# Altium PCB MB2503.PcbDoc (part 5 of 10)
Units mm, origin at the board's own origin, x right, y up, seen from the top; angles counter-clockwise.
Board outline 127 x 97 mm, 6 copper layers (Top Layer, Signal Layer 1, Signal Layer 2, Signal Layer 3, Signal Layer 4, Bottom Layer), stack 1.557 mm thick; 572 components, 468 nets, 2377 pads, 1704 vias.
Unrouted connection lines stored in the file: 3.
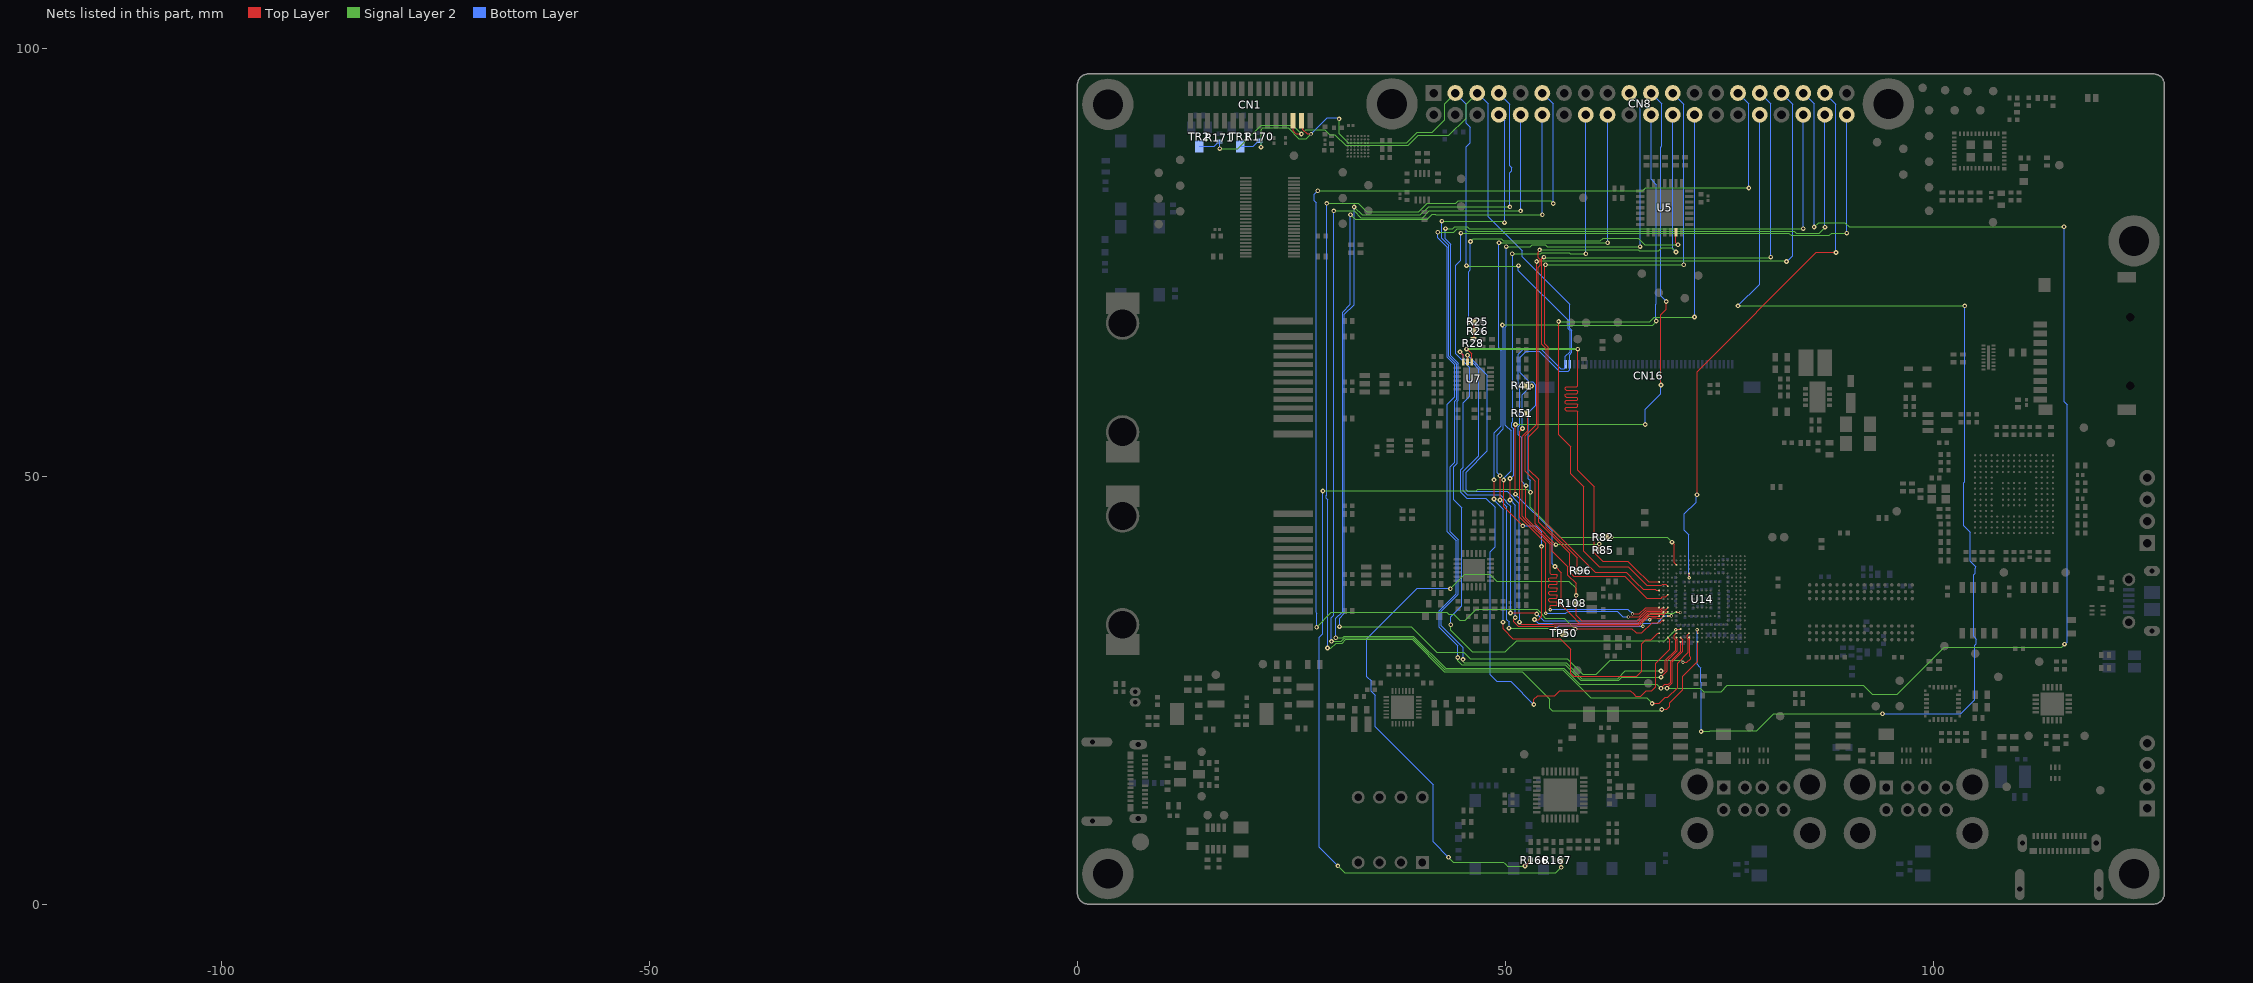
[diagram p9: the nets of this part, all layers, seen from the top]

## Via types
v1: diameter 0.55, hole 0.25, Top Layer to Bottom Layer, 1335 vias
v2: diameter 0.4, hole 0.2, Top Layer to Bottom Layer, 262 vias
v3: diameter 0.5, hole 0.2, Top Layer to Bottom Layer, 51 vias
v4: diameter 0.26, hole 0.1, Top Layer to Signal Layer 1, tented both sides, 29 vias
v5: diameter 0.5, hole 0.25, Top Layer to Bottom Layer, 18 vias
v6: diameter 0.4, hole 0.2, Top Layer to Bottom Layer, tented both sides, 9 vias

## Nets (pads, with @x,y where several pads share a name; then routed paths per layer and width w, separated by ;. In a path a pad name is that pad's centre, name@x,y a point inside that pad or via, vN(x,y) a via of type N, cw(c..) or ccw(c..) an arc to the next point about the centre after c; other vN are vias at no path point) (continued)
ETH2_NRST: R25.1 R26.1 R28.1 U5.27 | length 38.7
  Top Layer w0.1: v1(45.725,68.025) R25.1@46.35,68.025 R26.1@46.35,66.95 46.35,66.075 R28.1@46.275,66 ; U5.27@69.925,78.525 69.925,77.3 v1(70.175,77.05)
  Signal Layer 2 w0.1: v1(45.925,77.425) 46.225,77.725 49.5,77.725 49.725,77.5 61.1,77.5 61.425,77.825 65.5,77.825 66.275,77.05 v1(70.175,77.05)
  Bottom Layer w0.1: v1(45.725,68.025) 45.725,73.9 45.925,74.1 v1(45.925,77.425)
ETH2_RXD0: R41.1 U14.N2 | length 43.6
  Top Layer w0.075: 65.175,33.55 65.625,33.55 66.479,34.404 68.077,34.404 68.323,34.65 U14.N2@68.475,34.65
  Top Layer w0.1: v1(52,55.575) 51.7,55.275 51.7,45.2 54.725,42.175 v2(54.725,33.975) ; R41.1@52.425,60.575 52.45,60.55 v1(53.05,60.55) ; v2(64.375,33.55) 65.175,33.55
  Bottom Layer w0.1: v1(52,55.575) 52,59.5 v1(53.05,60.55) ; v2(54.725,33.975) 57.075,33.975 57.325,34.225 63.05,34.225 63.725,33.55 v2(64.375,33.55)
ETH2_RXD1: R51.1 U14.N1 | length 46.5
  Top Layer w0.075: 65.175,33.9 65.65,33.9 66.4,34.65 U14.N1@67.975,34.65
  Top Layer w0.1: R51.1@52.425,57.35 52.6,57.175 52.6,55.325 51.95,54.675 51.95,45.3 52.205,45.045 55.225,42.024 55.225,38.75 55.225,38.65 55.325,38.55 55.975,38.55 56.075,38.45 56.075,38.25 55.975,38.15 55.225,38.15 55.175,38.15 55.075,38.05 55.075,37.85 55.175,37.75 55.225,37.75 55.975,37.75 56.075,37.65 56.075,37.45 55.975,37.35 55.225,37.35 55.175,37.35 55.075,37.25 55.075,37.05 55.175,36.95 55.225,36.95 55.975,36.95 56.075,36.85 56.075,36.65 55.975,36.55 55.225,36.55 55.175,36.55 55.075,36.45 55.075,36.25 55.175,36.15 55.225,36.15 55.975,36.15 56.075,36.05 56.075,35.85 55.975,35.75 55.225,35.75 55.175,35.75 55.075,35.65 55.075,35.45 55.175,35.35 55.225,35.35 55.975,35.35 56.075,35.25 56.075,35.05 55.975,34.95 55.325,34.95 55.225,34.85 55.225,34.55 55.25,34.525 55.253,34.522 v2(55.253,34.402) ; v2(64.854,33.908) 64.863,33.9 65.175,33.9
  Bottom Layer w0.1: v2(55.253,34.402) 55.301,34.45 64.313,34.45 v2(64.854,33.908)
ETH2_TX_EN: U7.16 U14.G1 | length 58.9
  Top Layer w0.075: 65.175,39.2 66.725,37.65 U14.G1@67.975,37.65
  Top Layer w0.1: v1(45.45,64.85) 45.55,64.85 46.075,64.325 U7.16@46.075,63.35 ; v1(58.45,64.85) 58.45,60.975 58.45,60.85 58.45,60.55 58.35,60.45 57.125,60.45 57.025,60.35 57.025,60.15 57.125,60.05 58.35,60.05 58.45,59.95 58.45,59.75 58.35,59.65 57.125,59.65 57.025,59.55 57.025,59.35 57.125,59.25 58.35,59.25 58.45,59.15 58.45,58.95 58.35,58.85 57.125,58.85 57.025,58.75 57.025,58.55 57.125,58.45 58.35,58.45 58.45,58.35 58.45,58.15 58.35,58.05 57.125,58.05 57.025,57.95 57.025,57.75 57.125,57.65 58.35,57.65 58.45,57.55 58.45,57.45 58.45,50.675 60.375,48.75 60.375,41.05 61.375,40.05 64.325,40.05 65.175,39.2
  Signal Layer 2 w0.219: v1(45.45,64.85) v1(58.45,64.85)
ETH2_TXD0: U7.17 U14.P3 | length 57.4
  Top Layer w0.075: 65.175,32.7 65.575,32.7 66.772,33.897 68.572,33.897 68.825,34.15 U14.P3@68.975,34.15
  Top Layer w0.1: U7.17@45.575,63.35 v1(45.575,64.125) ; v1(51.653,32.952) 51.627,32.952 51.625,32.95 51.875,32.7 55.566,32.7 55.616,32.75 58.434,32.75 58.484,32.7 65.175,32.7
  Bottom Layer w0.1: v1(45.575,64.125) 47.9,61.8 47.9,52.95 45.4,50.45 45.4,48.4 45.575,48.225 50.2,48.225 51.625,46.8 51.625,44.401 51.6,44.376 51.6,34 51.653,33.947 v1(51.653,32.952)
ETH2_TXD1: U7.18 U14.R2 | length 56.9
  Top Layer w0.075: v2@66.898,33.225 66.905,33.225 67.161,33.481 67.644,33.481 67.725,33.4 68.225,33.4 U14.R2@68.475,33.65
  Top Layer w0.09: v2(66.875,33.225) v2@66.898,33.225
  Top Layer w0.1: v1(44.7,64.525) 45.075,64.15 U7.18@45.075,63.35 ; v1(50.6,34.025) 53.65,34.025 53.669,34.006 v1(53.669,33.9)
  Bottom Layer w0.1: v1(44.7,64.525) 45.1,64.125 45.1,63.85 45.641,63.309 46.108,63.309 46.9,62.517 46.9,52.4 45.1,50.6 45.1,48.275 45.55,47.825 49.4,47.825 50.125,47.1 50.125,46.95 50.6,46.475 v1(50.6,34.025) ; v1(53.669,33.9) 54.469,33.1 65.4,33.1 65.525,33.225 v2(66.875,33.225)
EXP_GPIO2: CN1.14 CN8.3 CN16.40 R108.1 R166.1 R170.2 TR1.3 U14.N3 | length 200.5
  Top Layer w0.075: 65.175,33.1 65.425,33.1 66.56,34.235 68.196,34.235 68.358,34.397 68.722,34.397 U14.N3@68.975,34.65
  Top Layer w0.09: v1(52.4,48.9) 52.4,45.125 55.475,42.05 55.475,41.225 57.3,39.4 57.3,38.45 58.275,37.475 R108.1@58.275,35.15 58.275,33.775 58.95,33.1 65.175,33.1
  Top Layer w0.1: CN1.14@26.2,91.525 26.304,91.421 26.304,90.509 26.825,89.987 27.287,89.987 v2(27.294,89.994) ; v1(52.3,4.45) R166.1@52.975,5.125
  Signal Layer 2 w0.1: v1(21.45,88.45) 21.45,90.475 21.675,90.7 24.625,90.7 25.875,89.45 26.75,89.45 v2(27.294,89.994) ; v1(30.573,91.75) 30.573,89.997 31.63,88.94 38.47,88.94 39.73,90.2 ; 39.95,90.2 39.73,90.2 ; v1(43.35,5.475) 43.925,4.9 49.775,4.9 49.9,4.775 ; v1(43.575,36.85) 45.25,38.525 48.2,38.525 48.975,37.75 57.425,37.75 58.275,36.9 v1(58.275,36.075) ; CN8.3@44.16,94.77 42.9,93.51 42.9,91.625 41.475,90.2 39.73,90.2 ; v1(45.45,74.6) 45.525,74.525 51.45,74.525 v1(51.525,74.6) ; 49.901,4.775 50.15,4.526 ; 50.15,4.525 50.225,4.45 v1(52.3,4.45)
  Bottom Layer w0.09: 51.9,51.5 51.9,49.4 v1(52.4,48.9)
  Bottom Layer w0.1: TR1.3@19,88.55 20.525,88.55 21.175,89.2 R170.2@21.3,89.2 21.45,89.05 v1(21.45,88.45) ; v2(27.294,89.994) 29.2,91.9 30.302,91.9 30.452,91.75 v1(30.573,91.75) ; 34.3,26.1 33.825,26.575 33.825,31.025 39.725,36.925 43.45,36.925 v1@43.475,36.95 ; 34.325,26.1 34.325,24.875 34.8,24.4 34.8,20.708 41.55,13.958 41.55,7.3 43.35,5.5 v1(43.35,5.475) ; CN8.3@44.16,94.77 45.45,93.48 45.45,91.214 45.914,90.75 45.914,88.957 45.45,88.493 v1(45.45,74.6) ; v1(51.525,74.6) 51.525,74 57.325,68.2 57.325,67.23 57.575,66.98 57.575,64.56 57.025,64.01 CN16.40@57.025,63.1 56.925,63 56.925,62.609 56.866,62.55 56.45,62.55 54.125,64.875 52.137,64.875 51.525,64.263 51.525,60.648 51.675,60.498 51.675,55.937 51.525,55.787 51.525,54.85 51.9,54.475 51.9,51.5
EXP_GPIO3: CN1.13 CN8.5 CN16.39 R82.1 R167.1 R171.2 TR2.3 U14.C5 | length 223.5
  Top Layer w0.075: v1(69.475,42.3) 69.721,42.054 69.721,39.904 U14.C5@69.975,39.65
  Top Layer w0.1: CN1.13@25.2,91.525 25.2,90.362 25.412,90.15 25.575,89.987 v1(26.163,89.987) ; v1@30.412,4.463 v1(30.425,4.475) ; v1(56.525,4.3) R167.1@56.525,5.125 ; R82.1@61.875,42.875 v2(62.45,42.875)
  Signal Layer 2 w0.09: 65.175,42.875 68.9,42.875 v1(69.475,42.3)
  Signal Layer 2 w0.1: v1(16.625,88.275) 18.75,88.275 21.48,91.005 25.145,91.005 v1(26.163,89.987) 26.671,90.496 28.907,90.496 29.477,89.925 30.085,89.925 31.36,88.65 38.63,88.65 39.83,89.85 43.4,89.85 45.4,91.85 45.4,93.47 CN8.5@46.7,94.77 ; v1(28.676,48.277) 46.573,48.277 46.575,48.275 46.775,48.475 52.575,48.475 v1(52.925,48.125) 52.925,46.35 56.4,42.875 v2(62.45,42.875) 65.175,42.875 ; v1(30.425,4.475) 31.25,3.65 55.875,3.65 v1(56.525,4.3)
  Bottom Layer w0.1: TR2.3@14.25,88.55 15.98,88.55 16.53,89.1 R171.2@16.625,89.1 v1(16.625,88.275) ; v1(28.676,48.277) 28.676,31.601 28.251,31.176 28.251,6.624 v1@30.4,4.475 ; CN8.5@46.7,94.77 47.975,93.495 47.975,80.325 51.95,76.35 51.95,75.65 57.525,70.075 57.525,67.313 57.775,67.063 57.775,64.46 57.525,64.21 CN16.39@57.525,63.1 57.525,62.451 57.336,62.262 56.288,62.262 53.975,64.575 52.425,64.575 51.725,63.875 51.725,62.106 52.787,61.044 53.181,61.044 53.575,60.65 53.575,58.3 52.7,57.425 52.7,49.725 52.925,49.5 v1(52.925,48.125)
EXP_GPIO4: CN8.7 U14.Y8 | length 129.6
  Top Layer w0.075: v2(70.75,28.25) 71.194,28.25 71.632,28.688 71.632,28.918 71.559,28.991 71.559,31.029 71.475,31.113 U14.Y8@71.475,31.15
  Signal Layer 2 w0.09: v1(30.625,32.425) 38.999,32.425 41.976,29.448 45.152,29.448 45.925,28.675 57.25,28.675 59.05,26.875 ; 41.023,81.475 v1(50.525,81.475) ; 65.175,28.514 70.536,28.514 70.775,28.275 v2@70.775,28.25
  Signal Layer 2 w0.1: v1(32.326,81.454) 32.351,81.454 33.28,80.525 40.073,80.525 41.023,81.475 ; 59.05,26.875 60.6,26.875 62.239,28.514 65.175,28.514
  Bottom Layer w0.09: v1(30.625,32.425) 30.625,33.425 31.2,34 31.2,68.9 32.326,70.026 v1(32.326,81.454) ; CN8.7@49.24,94.77 50.525,93.485 50.525,86.25 50.747,86.028 50.747,85.68 50.525,85.458 v1(50.525,81.475)
EXP_GPIO5: CN8.29 TP50.1 U14.T2 | length 159
  Top Layer w0.075: 65.175,31.8 65.275,31.7 65.947,31.7 67.151,32.904 67.466,32.904 68.077,32.904 68.3,33.127 68.452,33.127 U14.T2@68.475,33.15
  Top Layer w0.1: TP50.1@56.825,31.675 57.275,32.125 v1(58.175,32.125) 58.25,32.2 64.775,32.2 65.175,31.8
  Signal Layer 2 w0.1: v1(27.95,32.35) 29.675,34.075 43.15,34.075 43.375,33.85 43.975,33.85 44.65,33.175 45.33,33.175 46.605,34.45 47.975,34.45 53.72,34.45 54.3,33.87 54.3,33.799 54.674,33.425 56.875,33.425 56.95,33.35 ; v1(28.075,83.35) 66.075,83.35 66.425,83.7 78.425,83.7 v1(78.45,83.675) ; 56.95,33.349 v1(58.175,32.125)
  Bottom Layer w0.1: v1(27.95,32.35) 27.95,34 27.875,34.075 27.875,81.979 27.651,82.203 27.651,82.926 v1(28.075,83.35) ; CN8.29@77.18,94.77 78.45,93.5 v1(78.45,83.675)
EXP_GPIO6: CN8.31 R96.2 | length 85
  Top Layer w0.1: v1(54.5,75.6) 54.35,75.6 54.275,75.525 54.275,65.4 54.8,64.875 54.8,44.05 58.375,40.475 R96.2@58.375,38.95
  Signal Layer 2 w0.1: v1(54.5,75.6) 54.45,75.6 54.4,75.55 80.95,75.55 v1(81,75.6)
  Bottom Layer w0.1: CN8.31@79.72,94.77 81,93.49 v1(81,75.6)
EXP_GPIO7: CN8.26 U14.H3 | length 79.4
  Top Layer w0.075: 65.175,38.625 66.524,37.276 67.699,37.276 67.741,37.235 68.211,37.235 68.373,37.397 68.728,37.397 U14.H3@68.975,37.15
  Top Layer w0.1: v1(56.225,68.075) 56.225,54.85 57.65,53.425 57.65,50.275 59.15,48.775 59.15,41.25 60.975,39.425 64.375,39.425 65.175,38.625
  Signal Layer 2 w0.1: v1(56.225,68.075) 66.875,68.075 67.4,68.6 v1(72.1,68.6)
  Bottom Layer w0.1: v1(72.1,68.6) CN8.26@72.1,92.23
EXP_GPIO8: CN8.24 U14.K3 | length 85.8
  Top Layer w0.075: 65.175,37.075 66.515,35.735 68.185,35.735 68.354,35.904 68.729,35.904 U14.K3@68.975,36.15
  Top Layer w0.1: v1(54,76.45) 54,76.328 53.825,76.153 53.825,75.524 54.075,75.274 54.075,74.625 53.85,74.4 53.85,55.725 52.75,54.625 52.75,50.775 53.9,49.625 53.9,44.625 57.55,40.975 57.55,38.75 57.975,38.325 63.925,38.325 65.175,37.075
  Signal Layer 2 w0.1: v1(54,76.45) 65.524,76.45 65.649,76.325 67.907,76.325 68.282,76.7 69.425,76.7 v1(69.925,76.2)
  Bottom Layer w0.1: CN8.24@69.56,92.23 69.56,76.565 v1(69.925,76.2)
EXP_GPIO9: CN8.21 U14.P2 | length 92.6
  Top Layer w0.075: 65.175,32.9 65.515,32.9 66.681,34.066 68.266,34.066 68.327,34.127 68.452,34.127 U14.P2@68.475,34.15
  Top Layer w0.1: v1(51.175,47.9) v1(51.175,56.05) ; v1(55.8,39.45) 56.525,38.725 56.525,35.426 56.428,35.329 56.428,34.926 56.677,34.677 56.824,34.677 57.8,33.701 57.8,33.675 58.575,32.9 65.175,32.9 ; v1(68.175,60.65) 68.175,68.866 68.808,69.499 68.808,70.417 v1(68.8,70.425)
  Signal Layer 2 w0.1: v1(51.175,56.05) v1(66.35,56.05)
  Bottom Layer w0.1: v1(51.175,47.9) 55.475,43.6 55.475,39.775 v1(55.8,39.45) ; v1(66.35,56.05) 66.35,57.808 68.175,59.633 v1(68.175,60.65) ; CN8.21@67.02,94.77 68.3,93.49 68.3,88.595 68.15,88.445 68.15,71.075 v1(68.8,70.425)
EXP_GPIO10: CN8.19 U14.R3 | length 98.9
  Top Layer w0.09: U14.R3@68.975,33.65 68.988,33.663 69.388,33.663 v2(69.4,33.675)
  Top Layer w0.1: v1(49.8,49.55) 49.8,46.425 v1(52.025,44.2) ; v1(53.4,33.25) 53.9,33.25 54.275,33.625 54.275,41.325 54.225,41.375 v1(54.225,41.8)
  Signal Layer 2 w0.1: v1(50.1,76.825) 52.9,76.825 53.125,77.05 54.686,77.05 54.911,76.825 v1(65.75,76.825)
  Bottom Layer w0.09: 65.175,32.825 67.725,32.825 68.575,33.675 v2(69.4,33.675)
  Bottom Layer w0.1: v1(49.8,49.55) 49.8,49.775 50.675,50.65 50.675,55.3 50,55.975 50,67.424 50.075,67.499 50.075,76.8 v1(50.1,76.825) ; v1(52.025,44.2) 53.525,44.2 54.225,43.5 v1(54.225,41.8) ; v1(53.4,33.25) 53.825,32.825 65.175,32.825 ; CN8.19@64.48,94.77 65.75,93.5 v1(65.75,76.825)
EXP_GPIO11: CN8.23 U14.J1 | length 83.5
  Top Layer w0.075: 65.175,37.675 66.081,36.769 67.489,36.769 67.608,36.65 U14.J1@67.975,36.65
  Top Layer w0.1: v1(54.7,74.7) 54.614,74.614 54.614,74.43 54.6,74.416 54.6,65.475 55,65.075 55,44.25 60.5,38.75 64.1,38.75 65.175,37.675
  Signal Layer 2 w0.1: v1(54.7,74.7) v1(70.85,74.7)
  Bottom Layer w0.1: CN8.23@69.56,94.77 70.85,93.48 v1(70.85,74.7)
EXP_GPIO12: CN8.32 U14.W10 | length 142.9
  Top Layer w0.1: v2@72.4,32.05 72.438,32.05 72.465,32.077 72.465,31.66 U14.W10@72.475,31.65
  Signal Layer 2 w0.1: v1(72.875,20.175) 73.874,20.175 73.95,20.251 79.351,20.251 81.35,22.25 v1(94.075,22.25) ; v1(77.175,69.9) v1(103.675,69.9)
  Bottom Layer w0.09: v2(72.395,32.05) 72.395,28.005 72.675,27.725
  Bottom Layer w0.1: 72.675,27.725 72.8,27.6 72.8,25.95 72.875,25.875 v1(72.875,20.175) ; v1(77.175,69.9) 79.72,72.445 CN8.32@79.72,92.23 ; v1(94.075,22.25) 103.225,22.25 104.85,23.875 104.85,30.249 105.025,30.424 105.025,30.975 104.725,31.275 104.725,38.482 104.925,38.682 104.925,39.25 104.95,39.275 104.95,39.426 104.325,40.051 104.325,43.449 103.575,44.199 103.575,49.251 103.675,49.351 v1(103.675,69.9)
EXP_GPIO13: CN8.33 R85.1 | length 90.7
  Top Layer w0.09: v1(53.65,75.075) 53.65,56.05 52.325,54.725 52.325,50.55 53.475,49.4 53.475,44.425 v1(55.9,42) ; R85.1@60.975,41.375 v1(60.975,42.075)
  Signal Layer 2 w0.09: v1(53.65,75.075) 53.725,75.15 82.775,75.15 v1(82.85,75.075) ; v1(55.9,42) 55.975,42.075 v1(60.975,42.075)
  Bottom Layer w0.09: CN8.33@82.26,94.77 83.55,93.48 83.55,75.775 v1(82.85,75.075)
EXP_GPIO14: CN8.8 U14.W5 | length 104.9
  Top Layer w0.075: 68.7,27.725 68.7,28.497 69.89,29.687 69.89,30.86 69.725,31.025 69.725,31.4 U14.W5@69.975,31.65
  Top Layer w0.1: v1(68.175,27.25) 68.6,27.25 68.7,27.35 68.7,27.725
  Signal Layer 2 w0.09: v1(42.575,79.8) 49.607,79.8 49.778,79.629 v1(49.902,79.629)
  Signal Layer 2 w0.1: v1(45.046,28.604) 45.075,28.575 45.075,28.3 45.2,28.175 57.125,28.175 58.945,26.355 63.13,26.355 64.025,27.25 v1(68.175,27.25)
  Bottom Layer w0.09: v1(42.575,79.8) 42.575,77.8 43.4,76.975 43.4,64 44.305,63.095 44.305,58.981 44.1,58.776 44.1,51.655 43.55,51.105 43.55,43.525 44.475,42.6 44.475,36.2 42.5,34.225 42.5,32.526 44.999,30.027 45.025,30.001 v1(45.046,28.604) ; CN8.8@49.24,92.23 49.902,91.568 v1(49.902,79.629)
EXP_GPIO15: CN8.10 U14.W8 | length 135.7
  Top Layer w0.075: 70.12,27.725 70.12,28.17 71.39,29.44 71.39,30.885 71.225,31.05 71.225,31.4 U14.W8@71.475,31.65
  Top Layer w0.1: v1(67.15,23.45) 67.969,23.45 68.669,24.15 68.966,24.15 70.12,25.304 70.12,27.725
  Signal Layer 2 w0.1: v1(29.675,30.7) 30.833,30.7 31.258,31.125 39.174,31.125 42.924,27.375 56.7,27.375 59.975,24.1 66.5,24.1 v1(67.15,23.45) ; v1(29.95,81) 32.33,81 33.105,80.225 40.34,80.225 41.115,81 v1(51.78,81)
  Bottom Layer w0.1: v1(29.675,30.7) 29.675,33.45 29.95,33.725 v1(29.95,81) ; v1(51.78,81) CN8.10@51.78,92.23
EXP_GPIO16: CN8.36 U14.V6 | length 133
  Top Layer w0.09: v2(69.9,32.075) 69.948,32.123 70.448,32.123 U14.V6@70.475,32.15
  Signal Layer 2 w0.09: 65.175,30.8 68.625,30.8 v2(69.9,32.075)
  Signal Layer 2 w0.1: v1(43,78.925) 43.85,78.925 44.089,79.164 45.536,79.164 45.775,78.925 v1(84.8,78.925) ; v1(43.625,32.65) 43.625,32 46.15,29.475 50,29.475 51.325,30.8 65.175,30.8
  Bottom Layer w0.1: v1(43,78.925) 43,77.725 43.6,77.125 43.6,64.076 44.5,63.176 44.5,58.9 44.375,58.775 44.375,51.525 43.975,51.125 43.975,47.234 44.875,46.334 44.875,34.85 43.625,33.6 v1(43.625,32.65) ; v1(84.8,78.925) CN8.36@84.8,92.23
EXP_GPIO17: CN8.11 U14.AA10 | length 146.6
  Top Layer w0.075: 71.816,27.725 72.475,28.384 U14.AA10@72.475,30.65
  Top Layer w0.1: v1(68.275,22.75) 68.851,22.75 69.2,23.099 69.2,23.536 70.72,25.056 70.72,26.629 71.816,27.725
  Signal Layer 2 w0.1: v1(29.126,81.879) 32.784,81.879 33.788,80.875 39.9,80.875 40.9,81.875 44.2,81.875 44.5,82.175 55.3,82.175 v1(55.6,81.875) ; v1(29.212,29.921) 29.271,29.9 29.61,29.9 30.21,30.5 30.916,30.5 31.341,30.925 39.091,30.925 42.841,27.175 51.975,27.175 55.2,23.95 55.2,22.883 55.483,22.6 68.125,22.6 v1(68.275,22.75)
  Bottom Layer w0.1: v1(29.126,81.879) 29.126,47.803 29.076,47.753 29.076,47.401 29.225,47.253 29.225,29.934 v1(29.212,29.921) ; CN8.11@54.32,94.77 55.6,93.49 v1(55.6,81.875)
EXP_GPIO18: CN8.12 U14.AA6 | length 132
  Top Layer w0.075: 69.3,27.725 69.3,28.38 70.475,29.555 U14.AA6@70.475,30.65
  Top Layer w0.1: v1(68.175,25.225) 68.65,25.7 69.05,25.7 69.3,25.95 69.3,27.725
  Signal Layer 2 w0.09: v1(31.901,80.554) 31.946,80.554 32.47,80.03 40.886,80.03 41.476,80.62 41.824,80.62 41.894,80.55 v1(54.32,80.55)
  Signal Layer 2 w0.1: v1(30.175,31.125) 30.975,31.125 31.175,31.325 39.256,31.325 43.006,27.575 56.834,27.575 58.709,25.7 67.7,25.7 v1(68.175,25.225)
  Bottom Layer w0.09: v1(30.175,31.125) 30.175,33.375 30.975,34.175 30.975,69.175 31.901,70.101 v1(31.901,80.554) ; v1(54.32,80.55) CN8.12@54.32,92.23
EXP_GPIO19: CN8.35 U14.Y6 | length 151.5
  Top Layer w0.075: 69.5,27.725 69.5,28.341 70.725,29.566 70.725,30.9 U14.Y6@70.475,31.15
  Top Layer w0.1: v1@68.876,25.226 69.5,25.85 69.5,27.725
  Signal Layer 2 w0.09: v1@68.876,25.226 72.749,25.226 73.17,24.805 74.851,24.805 75.199,24.805 75.945,25.551 91.824,25.551 92.875,24.5 95.781,24.5 101.306,30.025 115.025,30.025 115.325,30.325 v1(115.325,30.375) ; v1(86.075,79.125) 86.1,79.125 86.6,79.625 89.675,79.625 90.175,79.125 115.25,79.125 v1(115.275,79.15)
  Bottom Layer w0.09: CN8.35@84.8,94.77 86.075,93.495 v1(86.075,79.125) ; v1(115.275,79.15) 115.275,58.675 115.625,58.325 115.625,30.625 115.375,30.375 v1(115.325,30.375)
  other v1: 68.874,25.226
EXP_GPIO20: CN8.38 U14.Y5 | length 142.7
  Top Layer w0.075: 68.9,27.725 68.9,28.458 70.059,29.617 70.059,30.93 69.998,30.991 69.998,31.127 U14.Y5@69.975,31.15
  Top Layer w0.1: v1(68.175,26.525) 68.9,27.25 68.9,27.725
  Signal Layer 2 w0.1: v1(42.1,78.5) 43.975,78.5 44.375,78.9 45.325,78.9 45.575,78.65 83.725,78.65 83.975,78.4 86.65,78.4 v1(87.35,79.1) ; v1(44.436,28.828) 44.436,28.439 44.9,27.975 57,27.975 58.82,26.155 63.255,26.155 63.625,26.525 v1(68.175,26.525)
  Bottom Layer w0.1: v1(42.1,78.5) 42.1,77.85 43.2,76.75 43.2,63.924 43.375,63.75 43.568,63.556 44.11,63.014 44.11,59.302 43.225,58.417 43.225,43.5 44.275,42.45 44.275,42.275 44.28,42.27 44.28,36.281 42.3,34.301 42.3,32.35 44.436,30.214 v1(44.436,28.828) ; CN8.38@87.34,92.23 87.34,79.11 v1(87.35,79.1)
EXP_GPIO21: CN8.40 U14.Y3 | length 144.3
  Top Layer w0.075: 67.55,27.725 67.55,28.125 69.225,29.8 69.225,30.9 U14.Y3@68.975,31.15
  Top Layer w0.1: v1@53.325,23.375 53.325,23.917 53.758,24.35 55.767,24.35 56.367,24.95 64.599,24.95 64.975,24.574 65.249,24.3 65.796,24.3 66.446,24.95 67.083,24.95 67.55,25.417 67.55,27.725
  Signal Layer 2 w0.1: v1(44.8,78.4) 83.1,78.4 83.375,78.125 87.85,78.125 88.125,78.4 v1(89.88,78.4)
  Bottom Layer w0.1: v1(44.8,78.4) 44.8,75.225 44.225,74.65 44.225,64.299 45.85,62.674 45.85,59.35 45.1,58.6 45.1,51.025 44.8,50.725 44.8,48.125 45.475,47.45 47.7,47.45 48.8,46.35 48.8,41.75 48.225,41.175 48.225,26.8 48.975,26.05 50.6,26.05 v1(53.325,23.325) ; v1(89.88,78.4) CN8.40@89.88,92.23
EXP_GPIO23: CN8.16 U14.R1 | length 86.3
  Top Layer w0.075: 65.175,32.5 65.625,32.5 66.775,33.65 U14.R1@67.975,33.65
  Top Layer w0.1: v1(50.55,47.225) v1(50.55,49.725) ; v1(51.15,33.5) 51.15,33.378 51,33.228 51,32.974 51.524,32.45 55.599,32.45 55.699,32.55 58.351,32.55 58.401,32.5 65.175,32.5
  Signal Layer 2 w0.1: v1(50.8,76) 54.151,76 54.276,76.125 57.457,76.125 57.582,76 v1(59.4,76)
  Bottom Layer w0.1: v1(50.55,47.225) 51.15,46.625 v1(51.15,33.5) ; v1(50.55,49.725) 50.95,50.125 50.95,55.525 50.75,55.725 50.75,55.874 50.75,56.226 50.875,56.351 50.875,75.925 v1(50.8,76) ; v1(59.4,76) CN8.16@59.4,92.23
EXP_GPIO24: CN8.18 U14.W1 | length 99.8
  Top Layer w0.075: 65.925,27.725 65.925,30.4 66.4,30.875 67.039,30.875 67.809,31.645 67.97,31.645 U14.W1@67.975,31.65
  Top Layer w0.1: v1(48.675,47.325) v1(48.675,49.575) ; v1(49.725,32.95) 49.725,32.15 50.875,31 56.425,31 57.65,29.775 57.65,26.975 58,26.625 65.325,26.625 65.925,27.225 65.925,27.725
  Signal Layer 2 w0.1: v1(49.25,77.275) v1(61.95,77.275)
  Bottom Layer w0.1: v1(48.675,47.325) 48.675,47.203 48.801,47.078 48.801,47.049 49.725,46.125 v1(49.725,32.95) ; v1(48.675,49.575) 48.675,55.05 49.525,55.9 49.525,64.675 49.2,65 49.2,77.225 v1(49.25,77.275) ; v1@61.94,77.275 CN8.18@61.94,92.23
EXP_GPIO25: CN8.22 U14.P5 | length 100.8
  Top Layer w0.09: U14.P5@69.975,34.15 70.002,34.123 70.406,34.123 v2(70.45,34.079)
  Top Layer w0.1: v1(49.375,47.225) v1(49.375,50.05)
  Signal Layer 2 w0.09: v2(66.075,32.475) 66.075,33.1 66.991,34.016 69.701,34.016 69.764,34.079 v2(70.45,34.079)
  Signal Layer 2 w0.1: v1(49.65,67.675) 56.024,67.675 56.049,67.65 67.2,67.65 67.628,68.078 v1(67.628,68.128) ; v1(50.425,32.25) 55.042,32.25 55.167,32.125 v1(55.875,32.125)
  Bottom Layer w0.09: 65.175,32.475 v2(66.075,32.475)
  Bottom Layer w0.1: v1(49.375,47.225) 50.175,46.425 50.175,33.225 50.425,32.975 v1(50.425,32.25) ; v1(49.375,50.05) 49.025,50.4 49.025,54.8 49.775,55.55 49.775,67.428 49.65,67.553 v1(49.65,67.675) ; v1(55.875,32.125) 56.3,32.55 58.351,32.55 58.426,32.475 65.175,32.475 ; CN8.22@67.02,92.23 67.02,84.68 67.625,84.075 67.625,70.151 67.575,70.101 67.575,68.181 v1(67.628,68.128)
EXP_GPIO26: CN8.37 U14.E8 | length 66.6
  Top Layer w0.09: v2(71.475,38.125) U14.E8@71.475,38.65
  Top Layer w0.1: v1(72.4,47.825) 72.4,62.225 86.325,76.15 v1(88.625,76.15)
  Bottom Layer w0.09: 71.425,43.125 71.425,38.175 v2(71.475,38.125)
  Bottom Layer w0.1: 71.425,43.125 71.425,43.175 70.925,43.675 70.925,45.6 72.275,46.95 72.275,47.578 72.4,47.703 v1(72.4,47.825) ; CN8.37@87.34,94.77 88.625,93.485 v1(88.625,76.15)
